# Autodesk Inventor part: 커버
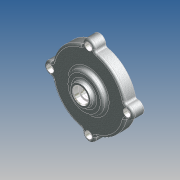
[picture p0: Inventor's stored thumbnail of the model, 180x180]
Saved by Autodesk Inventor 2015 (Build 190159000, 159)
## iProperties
Created: 2012-05
Part Number: 커버
Document SubType Name: 모델링
Designer: SeoGD™
Material: 일반
Appearance: 알루미늄 캐스트
변환 표준: STEP AP214IS
파일 이름: C:\Users\SeoGD\Desktop\?쒗뿕\而ㅻ쾭-1.stp
전처리기: Build: 253, Release: 2010 SP1 - Date: Wed 07/29/2009
전송 단위: 밀리미터
불확실성: 0.01
Author: SeoGD™
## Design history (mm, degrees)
sketch "스케치1"
  geometry: L1 (0, 0)-(0, 26); L2 (50, 0)-(50, 15); L3 (50, 15)-(25, 15); L4 (25, 15)-(25, 21); L5 (25, 21)-(15, 21); L6 (15, 21)-(13.66, 26); L7 (13.66, 26)-(10, 26); L8 (50, 0)-(45, 0); L9 (45, 0)-(45, 10); L10 (45, 10)-(14.5, 10); L11 (14.5, 10)-(13.266, 3); L12 (13.266, 3)-(11, 3); L13 (11, 3)-(11, 16); L14 (11, 16)-(7.5, 16); L15 (7.5, 16)-(7.5, 19); L16 (7.5, 19)-(10, 19); L17 (10, 19)-(10, 26)
  constraints: 34 end point, 10 parallel, 2 perpendicular, 2 point on line, 1 vertical
  dimensions: "d11" = 100 diameter of L2 L1; "d12" = 22 diameter of L13 L1; "d13" = 90 diameter of L9 L1; "d14" = 15 distance between parallel lines of L3 L8; "d15" = 10 distance between parallel lines of L8 L10; "d16" = 29 diameter of L10.end L1; "d17" = 100 deg angle of L11 L10; "d18" = 7 distance between parallel lines of L12 L10; "d19" = 13 distance between parallel lines of L14 L12; "d20" = 3 distance between parallel lines of L16 L14; "d21" = 15 diameter of L15 L1; "d22" = 20 diameter of L17 L1; "d23" = 30 diameter of L5.end L1; "d24" = 6 distance between parallel lines of L5 L3; "d25" = 50 diameter of L4 L1; "d26" = 105 deg angle of L5 L6; "d50" = 26 distance of L1.start L1.end
revolve "회전1" sketch "스케치1" stored, may be unused: angle "d27" = 90 deg
sketch "스케치2" dims "d29" = 104
  geometry: A1 r 8.5 centre (0, 52) between (8.074, 49.344) and (-8.074, 49.344); A2 r 50 centre (0, 0) between (-8.074, 49.344) and (8.074, 49.344) reference; 2 further points
  constraints: 4 point on circle, 2 vertical alignment, 1 centre point, 1 coincident, 2 other
  dimensions: "d28" = 17 diameter of A1
extrude "돌출1" join sketch "스케치2" stored distance "d30" = 10; taper "d31" = 0 deg
fillet "모깎기3" dims "d32" = 3
fillet "모깎기4" dims "d45" = 3, "d46" = 0.2
chamfer "모따기1" distance "d47" = 1; stored, may be unused: second distance "d48" = 2, angle "d49" = 45 deg
hole "구멍2" diameter "d38" = 5.5; stored, may be unused: countersink angle "d42" = 90 deg, drill point angle "d44" = 118 deg; dims "d36" = 10, "d37" = 10, "d39" = 6, "d40" = 9.5, "d41" = 5.4, "d43" = 8
node "솔리드1"
node "솔리드 본체"
node "곡면 본체"
pattern_circular "원형 패턴1" dims angle "d34" = 360 deg
pattern_circular "원형 패턴2" dims angle "d52" = 360 deg
node "솔리드2"
